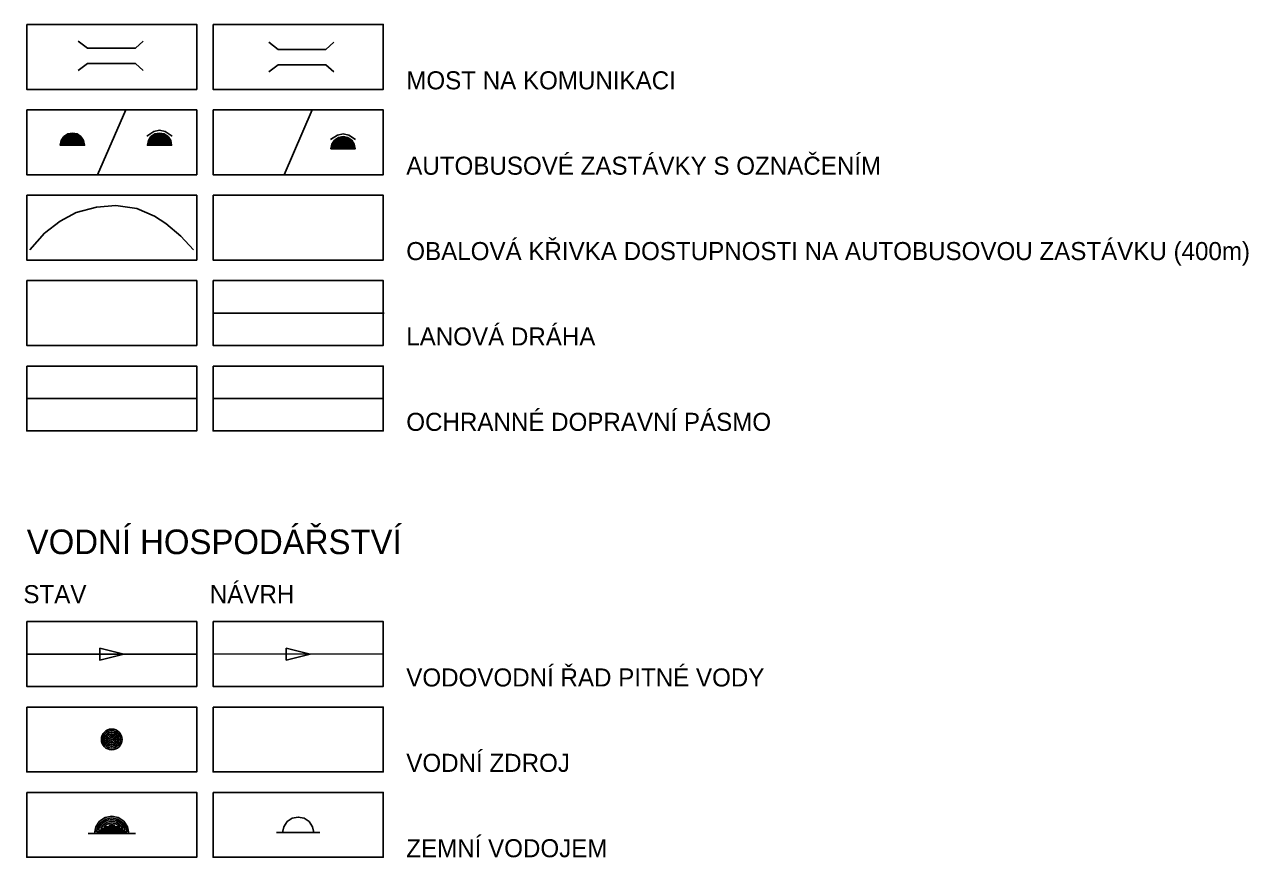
# Model space of a CAD drawing. Extents: x -439236 to -436242, y -1130161 to -1121098.
# Drawn here: x -439126 to -438380, y -1129059 to -1128552 of the extents above; entities that cross this region are included whole.
import ezdxf

# ---------------------------------------------------------------- set-up
doc = ezdxf.new("R2010")
doc.units = 0
for name, color, linetype in [('11930011_silniční most _ estakáda_Stav', 7, 'Continuous'), ('12600012_izochrona dostupnosti_Stav', 7, 'Continuous'), ('Vrstva 1', 7, 'Continuous'), ('Vrstva 10', 7, 'Continuous'), ('Vrstva 11', 7, 'Continuous'), ('Vrstva 12', 7, 'Continuous'), ('Vrstva 13', 7, 'Continuous'), ('Vrstva 14', 7, 'Continuous'), ('Vrstva 48', 7, 'Continuous'), ('Vrstva 54', 7, 'Continuous'), ('Vrstva 57', 7, 'Continuous'), ('Vrstva 6', 7, 'Continuous'), ('Vrstva 62', 7, 'Continuous'), ('Vrstva 7', 7, 'Continuous'), ('Vrstva 9', 7, 'Continuous')]:
    doc.layers.add(name, color=color, linetype=linetype)

msp = doc.modelspace()

# ---------------------------------------------------------------- linework, layer by layer
at = {"layer": '11930011_silniční most _ estakáda_Stav'}
for points in [[(-439093.45, -1128561.75), (-439087.87, -1128566.04), (-439058.68, -1128566.04), (-439053.96, -1128561.75)], [(-439093.45, -1128579.67), (-439087.87, -1128575.38), (-439058.68, -1128575.38), (-439053.96, -1128579.67)]]:
    msp.add_lwpolyline(points, dxfattribs=at)
at = {"layer": '12600012_izochrona dostupnosti_Stav'}
msp.add_lwpolyline([(-439122.93, -1128688.77), (-439113.96, -1128678.59), (-439104.45, -1128671.34), (-439094.69, -1128666.12), (-439082.41, -1128662.9), (-439070.53, -1128661.89), (-439057.85, -1128663.71), (-439046.97, -1128668.34), (-439040.12, -1128672.7), (-439031.07, -1128680.42), (-439023.24, -1128688.77)], dxfattribs=at)
at = {"layer": 'Vrstva 1'}
for p, q in [((-439081.69, -1128643.07), (-439064.48, -1128603.56)), ((-438968.07, -1128643.07), (-438950.87, -1128603.56))]:
    msp.add_line(p, q, dxfattribs=at)
for points in [[(-439124.89, -1128551.54), (-439021.28, -1128551.54), (-439021.28, -1128551.54), (-439021.28, -1128591.05), (-439124.89, -1128591.05)], [(-439011.28, -1128551.54), (-438907.66, -1128551.54), (-438907.66, -1128591.05), (-439011.28, -1128591.05)], [(-439124.89, -1128603.56), (-439021.28, -1128603.56), (-439021.28, -1128603.56), (-439021.28, -1128643.07), (-439124.89, -1128643.07)], [(-439011.28, -1128603.56), (-438907.66, -1128603.56), (-438907.66, -1128643.07), (-439011.28, -1128643.07)], [(-439124.89, -1128655.58), (-439021.28, -1128655.58), (-439021.28, -1128655.58), (-439021.28, -1128695.08), (-439124.89, -1128695.08)], [(-439011.28, -1128655.58), (-438907.66, -1128655.58), (-438907.66, -1128695.08), (-439011.28, -1128695.08)], [(-439124.89, -1128707.6), (-439021.28, -1128707.6), (-439021.28, -1128707.6), (-439021.28, -1128747.1), (-439124.89, -1128747.1)], [(-439011.28, -1128707.6), (-438907.66, -1128707.6), (-438907.66, -1128747.1), (-439011.28, -1128747.1)], [(-439124.89, -1128759.62), (-439021.28, -1128759.62), (-439021.28, -1128759.62), (-439021.28, -1128799.12), (-439124.89, -1128799.12)], [(-439011.28, -1128759.62), (-438907.66, -1128759.62), (-438907.66, -1128799.12), (-439011.28, -1128799.12)], [(-439124.89, -1128915.33), (-439021.28, -1128915.33), (-439021.28, -1128915.33), (-439021.28, -1128954.83), (-439124.89, -1128954.83)], [(-439011.28, -1128915.33), (-438907.66, -1128915.33), (-438907.66, -1128915.33), (-438907.66, -1128954.83), (-439011.28, -1128954.83)], [(-439124.89, -1128967.35), (-439021.28, -1128967.35), (-439021.28, -1128967.35), (-439021.28, -1129006.85), (-439124.89, -1129006.85)], [(-439011.28, -1128967.35), (-438907.66, -1128967.35), (-438907.66, -1129006.85), (-439011.28, -1129006.85)], [(-439124.89, -1129019.37), (-439021.28, -1129019.37), (-439021.28, -1129019.37), (-439021.28, -1129058.87), (-439124.89, -1129058.87)], [(-439011.28, -1129019.37), (-438907.66, -1129019.37), (-438907.66, -1129058.87), (-439011.28, -1129058.87)]]:
    msp.add_lwpolyline(points, close=True, dxfattribs=at)
at = {"layer": 'Vrstva 10'}
for p, q in [((-438972.6, -1129043.88), (-438969, -1129043.88)), ((-438946.34, -1129043.88), (-438949.94, -1129043.88))]:
    msp.add_line(p, q, dxfattribs=at)
msp.add_lwpolyline([(-438969, -1129043.88), (-438968.28, -1129040.24), (-438966.21, -1129037.14), (-438963.12, -1129035.08), (-438959.47, -1129034.35), (-438955.82, -1129035.08), (-438952.73, -1129037.14), (-438950.67, -1129040.24), (-438949.94, -1129043.88)], close=True, dxfattribs=at)
at = {"layer": 'Vrstva 11'}
msp.add_line((-439124.89, -1128935.08), (-439021.28, -1128935.08), dxfattribs=at)
at = {"layer": 'Vrstva 12'}
msp.add_lwpolyline([(-439080.38, -1128931.43), (-439080.38, -1128938.73), (-439065.79, -1128935.08)], close=True, dxfattribs=at)
at = {"layer": 'Vrstva 13'}
msp.add_line((-439011.28, -1128935.19), (-438907.66, -1128934.97), dxfattribs=at)
at = {"layer": 'Vrstva 14'}
msp.add_lwpolyline([(-438966.77, -1128931.43), (-438966.76, -1128938.73), (-438952.17, -1128935.05)], close=True, dxfattribs=at)
at = {"layer": 'Vrstva 48'}
msp.add_line((-439011.78, -1128727.35), (-438907.16, -1128727.35), dxfattribs=at)
at = {"layer": 'Vrstva 54'}
for points in [[(-439097.05, -1128617.69), (-439094.22, -1128618.25), (-439091.83, -1128619.85), (-439090.23, -1128622.25), (-439089.66, -1128625.08), (-439104.44, -1128625.08), (-439103.87, -1128622.25), (-439102.28, -1128619.85), (-439099.88, -1128618.25)], [(-439097.05, -1128618.25), (-439094.44, -1128618.77), (-439092.22, -1128620.25), (-439090.74, -1128622.46), (-439090.33, -1128624.53), (-439103.77, -1128624.53), (-439103.36, -1128622.46), (-439101.88, -1128620.25), (-439099.67, -1128618.77)], [(-439097.05, -1128618.81), (-439094.65, -1128619.28), (-439092.62, -1128620.64), (-439091.26, -1128622.68), (-439091, -1128623.98), (-439103.1, -1128623.98), (-439102.84, -1128622.68), (-439101.49, -1128620.64), (-439099.45, -1128619.28)], [(-439097.05, -1128619.36), (-439094.86, -1128619.8), (-439093.01, -1128621.04), (-439091.77, -1128622.89), (-439091.66, -1128623.44), (-439102.44, -1128623.44), (-439102.33, -1128622.89), (-439101.09, -1128621.04), (-439099.24, -1128619.8)], [(-439043.95, -1128617.69), (-439041.12, -1128618.25), (-439038.73, -1128619.85), (-439037.13, -1128622.25), (-439036.56, -1128625.08), (-439051.34, -1128625.08), (-439050.77, -1128622.25), (-439049.17, -1128619.85), (-439046.78, -1128618.25)], [(-439043.95, -1128618.25), (-439041.34, -1128618.77), (-439039.12, -1128620.25), (-439037.64, -1128622.46), (-439037.23, -1128624.53), (-439050.67, -1128624.53), (-439050.26, -1128622.46), (-439048.78, -1128620.25), (-439046.56, -1128618.77)], [(-439043.95, -1128618.8), (-439041.55, -1128619.28), (-439039.52, -1128620.64), (-439038.16, -1128622.68), (-439037.9, -1128623.98), (-439050, -1128623.98), (-439049.74, -1128622.68), (-439048.38, -1128620.64), (-439046.35, -1128619.28)], [(-439043.95, -1128619.36), (-439041.76, -1128619.8), (-439039.91, -1128621.04), (-439038.67, -1128622.89), (-439038.56, -1128623.44), (-439049.34, -1128623.44), (-439049.23, -1128622.89), (-439047.99, -1128621.04), (-439046.14, -1128619.8)], [(-439097.05, -1128619.92), (-439095.08, -1128620.31), (-439093.41, -1128621.43), (-439092.43, -1128622.89), (-439101.67, -1128622.89), (-439100.7, -1128621.43), (-439099.02, -1128620.31)], [(-439097.05, -1128620.48), (-439095.29, -1128620.83), (-439093.8, -1128621.83), (-439093.46, -1128622.34), (-439100.65, -1128622.34), (-439100.3, -1128621.83), (-439098.81, -1128620.83)], [(-439097.05, -1128621.04), (-439095.5, -1128621.35), (-439094.83, -1128621.79), (-439099.27, -1128621.8), (-439098.6, -1128621.35)], [(-439043.95, -1128619.92), (-439041.98, -1128620.31), (-439040.3, -1128621.43), (-439039.33, -1128622.89), (-439048.57, -1128622.89), (-439047.6, -1128621.43), (-439045.92, -1128620.31)], [(-439043.95, -1128620.48), (-439042.19, -1128620.83), (-439040.7, -1128621.83), (-439040.36, -1128622.34), (-439047.55, -1128622.34), (-439047.2, -1128621.83), (-439045.71, -1128620.83)], [(-439043.95, -1128621.04), (-439042.4, -1128621.34), (-439041.73, -1128621.79), (-439046.17, -1128621.79), (-439045.5, -1128621.35)]]:
    msp.add_lwpolyline(points, close=True, dxfattribs=at)
msp.add_lwpolyline([(-439051.59, -1128619.5), (-439047.42, -1128616.71), (-439043.95, -1128616.01), (-439040.48, -1128616.71), (-439036.31, -1128619.5)], dxfattribs=at)
at = {"layer": 'Vrstva 57'}
for points in [[(-438977.33, -1128562.41), (-438971.75, -1128566.71), (-438942.57, -1128566.71), (-438937.84, -1128562.41)], [(-438977.33, -1128580.33), (-438971.75, -1128576.04), (-438942.57, -1128576.04), (-438937.84, -1128580.33)]]:
    msp.add_lwpolyline(points, dxfattribs=at)
at = {"layer": 'Vrstva 6'}
msp.add_line((-439021.28, -1128779.37), (-439124.89, -1128779.37), dxfattribs=at)
at = {"layer": 'Vrstva 62'}
msp.add_lwpolyline([(-438939.73, -1128621.69), (-438935.56, -1128618.9), (-438932.09, -1128618.2), (-438928.62, -1128618.9), (-438924.45, -1128621.69)], dxfattribs=at)
for points in [[(-438932.09, -1128619.88), (-438929.26, -1128620.44), (-438926.87, -1128622.04), (-438925.27, -1128624.44), (-438924.7, -1128627.27), (-438939.48, -1128627.27), (-438938.91, -1128624.44), (-438937.31, -1128622.04), (-438934.92, -1128620.44)], [(-438932.09, -1128620.44), (-438929.48, -1128620.96), (-438927.26, -1128622.44), (-438925.78, -1128624.65), (-438925.37, -1128626.72), (-438938.81, -1128626.72), (-438938.4, -1128624.65), (-438936.92, -1128622.44), (-438934.7, -1128620.96)], [(-438932.09, -1128620.99), (-438929.69, -1128621.47), (-438927.66, -1128622.83), (-438926.3, -1128624.87), (-438926.04, -1128626.17), (-438938.14, -1128626.17), (-438937.88, -1128624.87), (-438936.52, -1128622.83), (-438934.49, -1128621.47)], [(-438932.09, -1128621.55), (-438929.9, -1128621.99), (-438928.05, -1128623.23), (-438926.81, -1128625.08), (-438926.7, -1128625.63), (-438937.48, -1128625.63), (-438937.37, -1128625.08), (-438936.13, -1128623.23), (-438934.28, -1128621.99)], [(-438932.09, -1128622.11), (-438930.12, -1128622.5), (-438928.44, -1128623.62), (-438927.47, -1128625.08), (-438936.71, -1128625.08), (-438935.74, -1128623.62), (-438934.06, -1128622.5)], [(-438932.09, -1128622.67), (-438930.33, -1128623.02), (-438928.84, -1128624.02), (-438928.5, -1128624.53), (-438935.69, -1128624.53), (-438935.34, -1128624.02), (-438933.85, -1128623.02)], [(-438932.09, -1128623.23), (-438930.54, -1128623.53), (-438929.87, -1128623.98), (-438934.31, -1128623.98), (-438933.64, -1128623.54)]]:
    msp.add_lwpolyline(points, close=True, dxfattribs=at)
at = {"layer": 'Vrstva 7'}
msp.add_line((-439011.28, -1128779.37), (-438907.66, -1128779.37), dxfattribs=at)
at = {"layer": 'Vrstva 9'}
for p, q in [((-439087.49, -1129044.34), (-439083.54, -1129044.34)), ((-439058.69, -1129044.34), (-439062.64, -1129044.34))]:
    msp.add_line(p, q, dxfattribs=at)
for points in [[(-439083.54, -1129044.34), (-439082.74, -1129040.34), (-439080.48, -1129036.95), (-439077.09, -1129034.69), (-439073.09, -1129033.89), (-439069.09, -1129034.69), (-439065.7, -1129036.95), (-439063.43, -1129040.34), (-439062.64, -1129044.34)], [(-439082.32, -1129043.34), (-439081.8, -1129040.73), (-439079.75, -1129037.67), (-439076.7, -1129035.63), (-439073.09, -1129034.91), (-439069.48, -1129035.63), (-439066.42, -1129037.67), (-439064.37, -1129040.73), (-439063.85, -1129043.34)], [(-439081.1, -1129042.34), (-439080.86, -1129041.12), (-439079.03, -1129038.4), (-439076.3, -1129036.57), (-439073.09, -1129035.93), (-439069.87, -1129036.57), (-439067.14, -1129038.4), (-439065.32, -1129041.12), (-439065.07, -1129042.34)], [(-439079.8, -1129041.34), (-439078.31, -1129039.12), (-439075.91, -1129037.51), (-439073.09, -1129036.95), (-439070.26, -1129037.51), (-439067.86, -1129039.12), (-439066.37, -1129041.34)], [(-439077.93, -1129040.34), (-439077.59, -1129039.84), (-439075.52, -1129038.46), (-439073.09, -1129037.97), (-439070.65, -1129038.46), (-439068.58, -1129039.84), (-439068.24, -1129040.34)], [(-439074.86, -1129039.34), (-439073.09, -1129038.99), (-439071.32, -1129039.34)]]:
    msp.add_lwpolyline(points, close=True, dxfattribs=at)
for radius in [6.3, 5.3, 4.3, 3.3, 2.3, 1.3, 0.3]:
    msp.add_circle((-439073.09, -1128987.1), radius, dxfattribs=at)

# ---------------------------------------------------------------- texts
at = {"layer": 'Vrstva 1'}
for s, height, p in [('MOST NA KOMUNIKACI', 11, (-438893.61, -1128591.05)), ('AUTOBUSOVÉ ZASTÁVKY S OZNAČENÍM', 11, (-438893.61, -1128643.07)), ('OBALOVÁ KŘIVKA DOSTUPNOSTI NA AUTOBUSOVOU ZASTÁVKU (400m)', 11, (-438893.61, -1128695.08)), ('LANOVÁ DRÁHA', 11, (-438893.61, -1128747.1)), ('OCHRANNÉ DOPRAVNÍ PÁSMO', 11, (-438893.61, -1128799.12)), ('VODNÍ HOSPODÁŘSTVÍ', 15, (-439124.89, -1128874.21)), ('STAV', 11, (-439126.91, -1128904.08)), ('NÁVRH', 11, (-439013.3, -1128904.08)), ('VODOVODNÍ ŘAD PITNÉ VODY', 11, (-438893.61, -1128954.83)), ('VODNÍ ZDROJ', 11, (-438893.61, -1129006.85)), ('ZEMNÍ VODOJEM', 11, (-438893.61, -1129058.87))]:
    msp.add_text(s, height=height, dxfattribs=at).set_placement(p)

doc.saveas('drawing.dxf')
